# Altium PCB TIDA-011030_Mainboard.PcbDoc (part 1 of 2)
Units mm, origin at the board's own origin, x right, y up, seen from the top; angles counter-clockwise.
Board outline 65 x 19.54 mm, 4 copper layers (Top Layer, Inner Layer 1, Inner Layer 2, Bottom Layer), stack 1.586 mm thick; 113 components, 53 nets, 288 pads, 190 vias.
Unrouted connection lines stored in the file: 190.
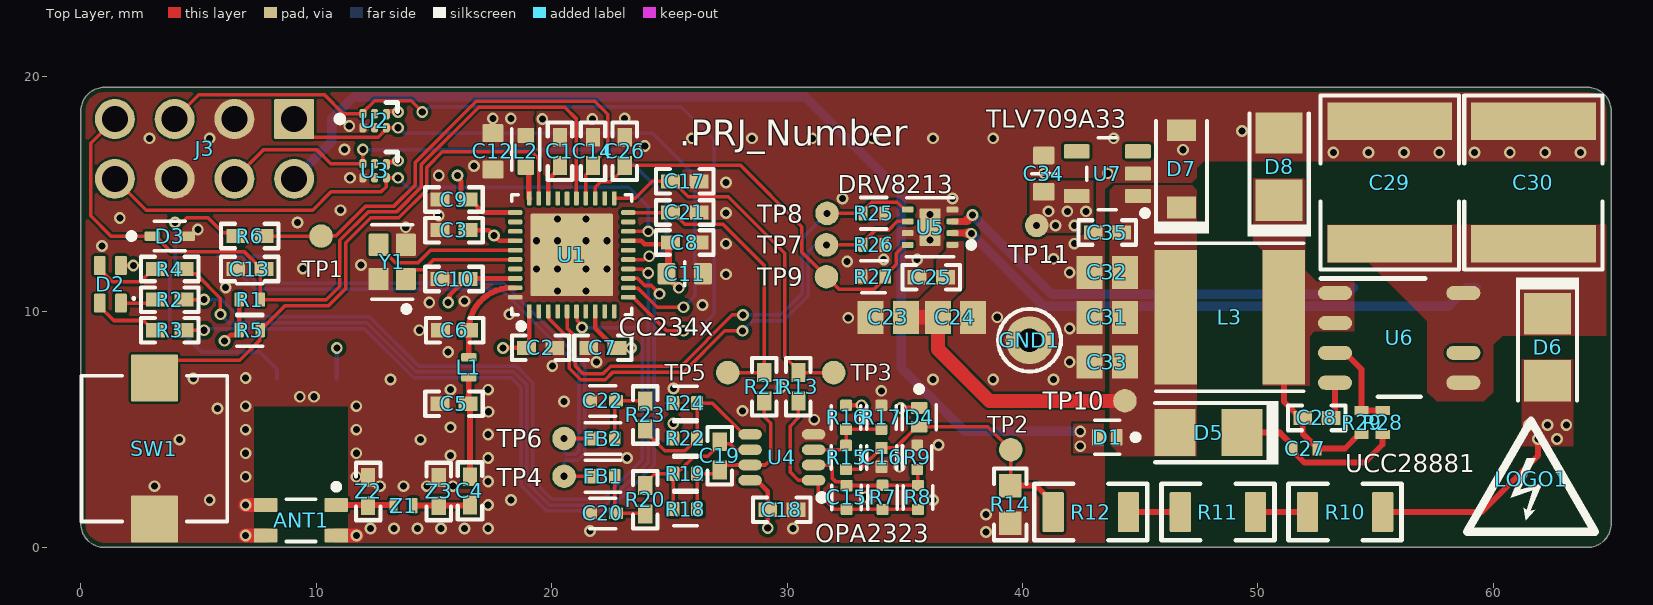
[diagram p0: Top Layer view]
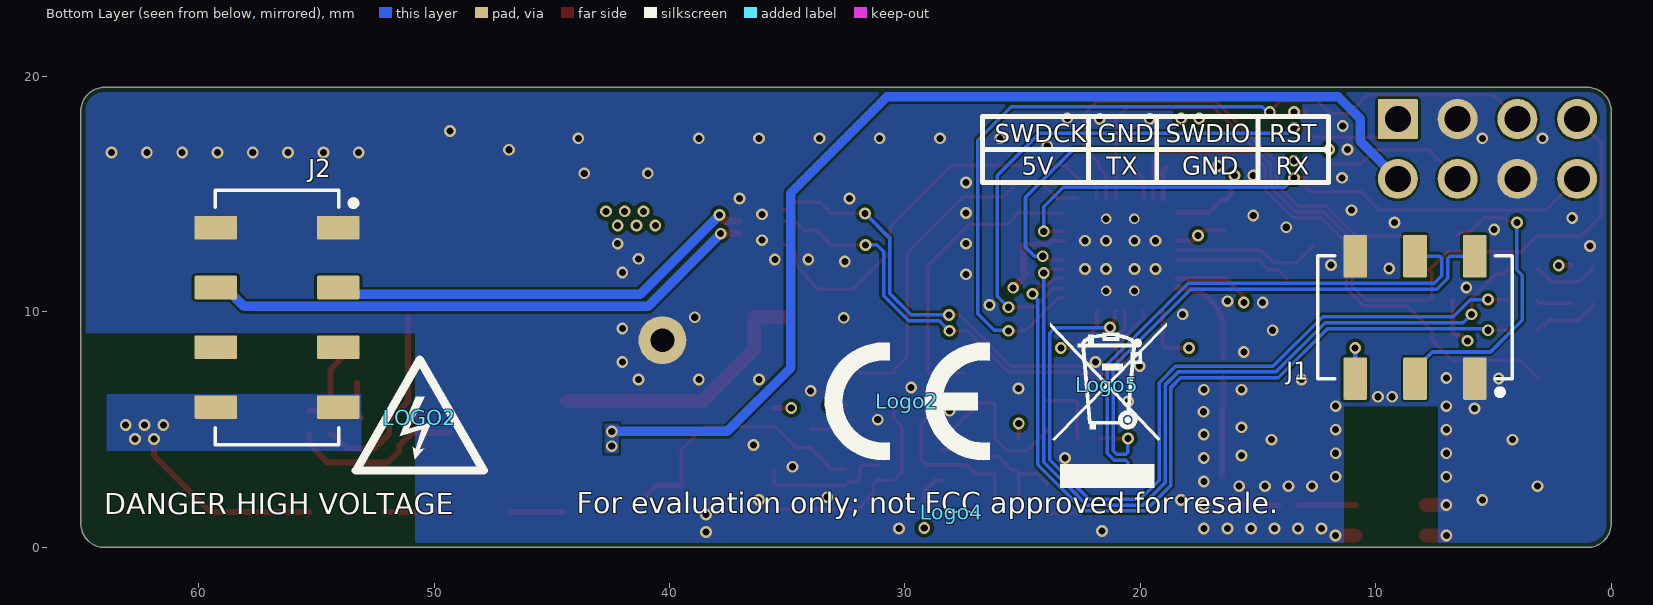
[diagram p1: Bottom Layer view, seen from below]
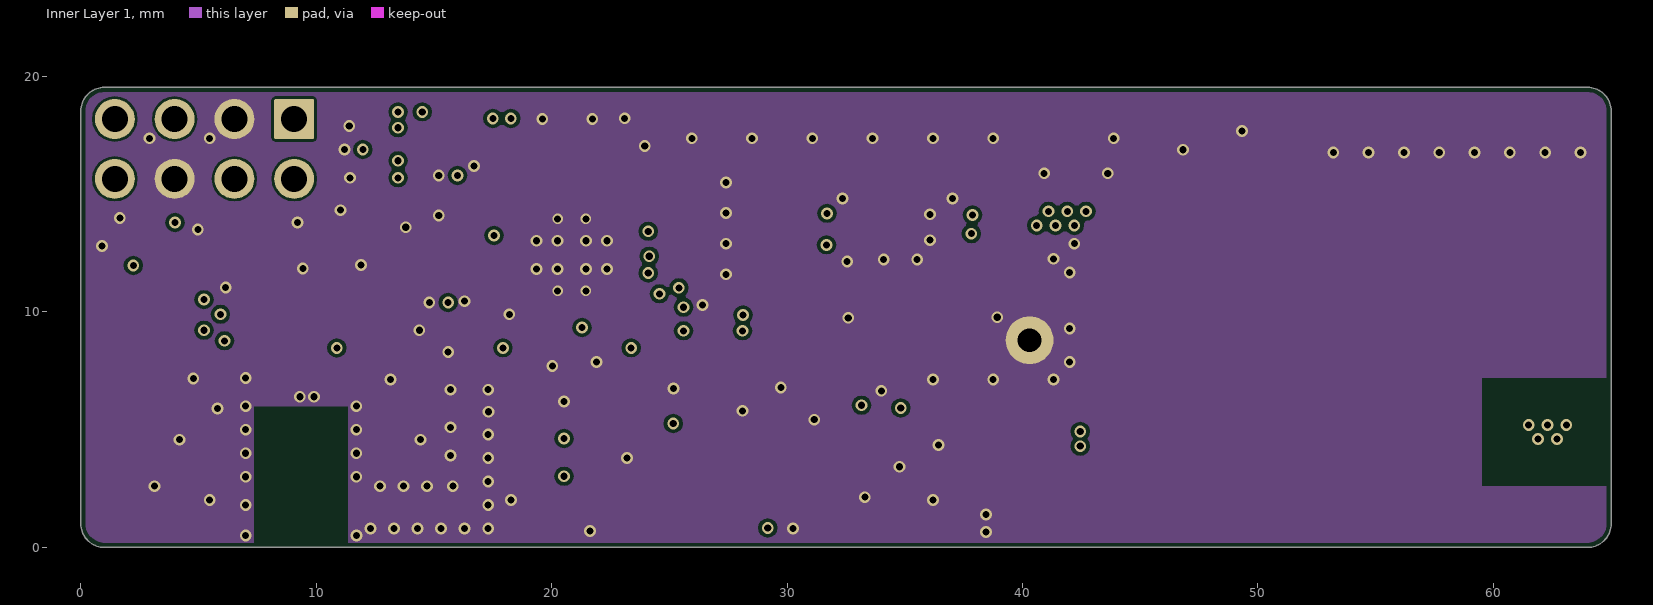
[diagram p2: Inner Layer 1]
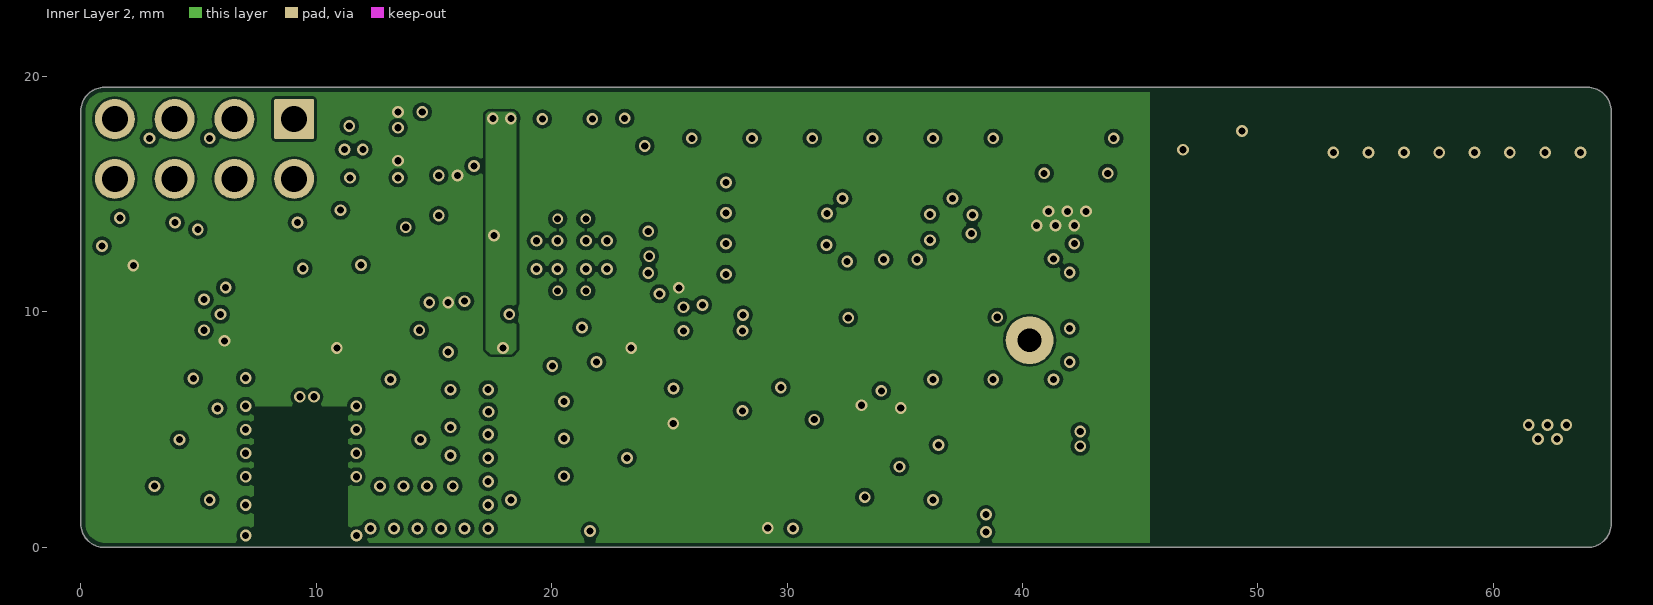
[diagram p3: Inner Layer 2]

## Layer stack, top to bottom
Top Solder: solder mask 0.0152, Solder Resist, Dk 3.8
Top Layer: signal copper 0.035
Dielectric 1: prepreg 0.2104, NP-155F, Dk 4.4
Inner Layer 1: signal copper 0.0152
Dielectric 2: core 1.065, NP-155F, Dk 4.43
Inner Layer 2: signal copper 0.0152
Dielectric 3: prepreg 0.2104, NP-155F, Dk 4.4
Bottom Layer: signal copper 0.035
Bottom Solder: solder mask 0.0152, Solder Resist, Dk 3.8

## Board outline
0,1 0,18.54 cw(c1,18.54) 1,19.54 64,19.54 cw(c64,18.54) 65,18.54 65,1 cw(c64,1) 64,0 1,0 cw(c1,1)

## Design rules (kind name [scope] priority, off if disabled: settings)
BoardOutlineClearance [All] p1: gap=0.2 ignorepadtopadclearanceinfootprint=FALSE
Clearance [All] p1: gap=0.102 ignorepadtopadclearanceinfootprint=FALSE except(0.127: Arc-Via Track-Via SMDPad-Via THPad-Via Via-Via Via-Fill Via-Poly Via-Region Via-Text; 0.25: Arc-Hole Track-Hole SMDPad-Hole THPad-Hole Via-Hole Fill-Hole Poly-Hole Region-Hole Text-Hole)
ComponentClearance [All] p1: gap=0.102 collisioncheckmode=3 verticalgap=0.102 showdistances=TRUE
DiffPairsRouting [All] p1: maxlimit=0.102 minlimit=0.102 mostfreqgap=0.102 toplayer_minwidth=0.102 toplayer_maxwidth=1816.048 toplayer_prefwidth=0.102 midlayer1_minwidth=0.102 midlayer1_maxwidth=1816.048 midlayer1_prefwidth=0.102 midlayer2_minwidth=0.102 midlayer2_maxwidth=1816.048 midlayer2_prefwidth=0.102 bottomlayer_minwidth=0.102 bottomlayer_maxwidth=1816.048 bottomlayer_prefwidth=0.102 maxuncoupledlength=12.7
Height [All] p1: minheight=0 maxheight=1816.048 prefheight=12.7
HoleSize [All] p1: absolutevalues=TRUE maxlimit=6.3 minlimit=0.2 maxpercent=80.000 minpercent=20.000
HoleToHoleClearance [All] p1: gap=0.25 allowstackedmicrovias=FALSE
MaxMinImpedance 50OHM [All] p1: minimum=48.00 maximum=52.00
MinimumAnnularRing [All] p1: minimumring=0.076
MinimumSolderMaskSliver [All] p1: minsoldermaskwidth=0
PlaneClearance [All] p1: clearance=0.102
PlaneConnect PlaneConnectPowerPads [InPadClass('PowerPads')] p1: planeconnectstyle=Direct reliefexpansion=0.508 reliefentries=4 reliefconductorwidth=0.254 reliefairgap=0.254
PlaneConnect [All] p2: pad.planeconnectstyle=Relief pad.reliefexpansion=0.3 pad.reliefentries=4 pad.reliefconductorwidth=0.102 pad.reliefairgap=0.102 via.planeconnectstyle=Direct via.reliefexpansion=0.3 via.reliefentries=4 via.reliefconductorwidth=0.127 via.reliefairgap=0.127
PolygonConnect PolygonConnectPowerPads [All vs (InPadClass('PowerPads'))] p1: connectstyle=Direct reliefconductorwidth=0.254 reliefentries=4 polygonreliefangle="90 Angle" airgapwidth=0.254
PolygonConnect [All] p2: thpad.connectstyle=Relief thpad.reliefconductorwidth=0.102 thpad.reliefentries=4 thpad.polygonreliefangle="90 Angle" thpad.airgapwidth=0.102 smdpad.connectstyle=Relief smdpad.reliefconductorwidth=0.102 smdpad.reliefentries=4 smdpad.polygonreliefangle="90 Angle" smdpad.airgapwidth=0.102 via.connectstyle=Direct via.reliefconductorwidth=0.127 via.reliefentries=4 via.polygonreliefangle="90 Angle" via.airgapwidth=0.127
RoutingVias [All] p1: holewidth=0.3 width=0.5 viastyle="Through Hole" minholewidth=0.2 minwidth=0.45 maxholewidth=6.3 maxwidth=6.55
SilkToBoardRegionClearance [Not ((IsComment or IsDesignator) And (Hide <> 'False')) and not InRegion(1000,500,4000,800)] p1:
SilkToSilkClearance [All] p1: silktosilkclearance=0
SilkToSolderMaskClearance [IsPad] p1: minsilkscreentomaskgap=0.102 clearancetoexposedcopper=TRUE
SolderMaskExpansion [All] p1: expansion=0.075 istentingtop=FALSE
SupplyNets "Schematic Supply Nets_4" [InNet('GND')] p1: voltage=0.000
SupplyNets "Schematic Supply Nets_3" [InNet('3.3V')] p2: voltage=0.000
SupplyNets "Schematic Supply Nets_1" [InNet('VDDR')] p3: voltage=0.000
SupplyNets "Schematic Supply Nets" [InNet('5V')] p4: voltage=0.000
Width "50 OHM" [InNetClass('50OHM')] p1: maxlimit=0.358 minlimit=0.1 preferedwidth=0.248 midlayer1_maxwidth=0.274 midlayer1_prefwidth=0.186 midlayer2_maxwidth=0.274 midlayer2_prefwidth=0.186 bottomlayer_maxwidth=0.357 impedanceprofiledriven=TRUE impedanceprofileid={30C50C51-8CC3-4552-90F9-A8ABCBFF07AD} impedanceprofilevalue=50.000000 minimp=50.000000 maximp=50.000000 favimp=50.000000
Width [All] p2: maxlimit=1816.048 minlimit=0.102 preferedwidth=0.102
19 further rules are at their usual default settings.

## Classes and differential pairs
net class HV: Line NetC27_2 NetC29_1
component class TIDA-011030_Mainboard_RelayDRV: C23 C24 C25 C26 R25 R26 R27 TP7 TP8 TP9 U5
component class TIDA-011030_Mainboard_Metering: C15 C16 C17 C18 C19 C20 C21 C22 D4 FB1 FB2 R7 R8 R9 R10 R11 R12 R13 R14 R15 R16 R17 R18 R19 R20 R21 R22 R23 R24 TP2 TP3 TP4 TP5 TP6 U4
component class TIDA-011030_Mainboard_Power: C27 C28 C29 C30 C31 C32 C33 C34 C35 D5 D6 D7 D8 L3 R28 R29 TP10 TP11 U6 U7
component class TIDA-011030_Mainboard_MCU: ANT1 C1 C2 C3 C4 C5 C6 C7 C8 C9 C10 C11 C12 C13 C14 D1 D2 D3 J1 J2 J3 L1 L2 R1 R2 R3 R4 R5 R6 SW1 TP1 U1 U2 U3 Y1 Z1 Z2 Z3
component class TIDA-011030_Mainboard_Hardware: GND1 LOGO1 Logo2 LOGO2 Logo4 Logo5 ZZ1 ZZ2 ZZ3
component class AssemblyNote: ZZ1 ZZ2 ZZ3
differential pair I: +I_P -I_N

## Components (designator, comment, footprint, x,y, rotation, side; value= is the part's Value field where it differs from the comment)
ANT1 "2450AT18D0100001E" FP-2450AT18D0100001E_1206-MFG 9.35,1.15 r180 top
C1 "GCM155R71C104KA55D" 0402 20.35,16.825 r270 top value=0.1uF
C2 "GCM155R71C104KA55D" 0402 19.525,8.475 r0 top value=0.1uF
C3 "GCM155R71C104KA55D" 0402 15.85,13.475 r180 top value=0.1uF
C4 "04025A150FAT2A" 0402 16.525,2.4 r270 top value=15pF
C5 "GRM1555C1H1R5CA01D" 0402 15.85,6.1 r180 top value=1.5pF
C6 "GRM1555C1H1R5CA01D" 0402 15.875,9.225 r180 top value=1.5pF
C7 "GCM155R71C104KA55D" 0402 22.175,8.475 r180 top value=0.1uF
C8 "GCM155R71C104KA55D" 0402 25.65,12.95 r0 top value=0.1uF
C9 "GCM155R71C104KA55D" 0402 15.85,14.775 r180 top value=0.1uF
C10 "GCM155R71C104KA55D" 0402 15.85,11.4 r180 top value=0.1uF
C11 "GRT188D71A106ME13D" FP-GRT188D71A106ME13D_0603-MFG 25.65,11.625 r0 top value=10µF
C12 "GRT188D71A106ME13D" FP-GRT188D71A106ME13D_0603-MFG 17.5,16.825 r270 top value=10µF
C13 "GCM155R71C104KA55D" 0402 7.175,11.825 r180 top value=0.1uF
C14 "GRM155R71H681KA01D" 0402 21.75,16.825 r90 top value=680pF
C15 "885012005058" FP-885012005058_0402-MFG 32.527,2.121 r270 top value=33pF
C16 "C0402C222F3GAC7867" FP-C0402C222F3GAC7867_0402-MFG 34.013,3.825 r90 top value=2.2nF
C17 "GRM155R71H681KA01D" 0402 25.65,15.55 r0 top value=680pF
C18 "GCM155R71C104KA55D" 0402 29.775,1.6 r0 top value=0.1uF
C19 "GRM1555C1H471JA01D" 0402 27.138,3.89 r90 top value=470pF
C20 "04025A101JAT2A" FP-04025A101JAT2A_0402-MFG 22.175,1.446 r0 top value=100pF
C21 "GRM155R71H681KA01D" 0402 25.65,14.229 r0 top value=680pF
C22 "04025A101JAT2A" FP-04025A101JAT2A_0402-MFG 22.175,6.225 r180 top value=100pF
C23 "GRM21BR61A476ME15L" 0805L 34.298,9.775 r180 top value=47uF
C24 "GRM21BR61A476ME15L" 0805L 37.15,9.775 r0 top value=47uF
C25 "GCM155R71C104KA55D" 0402 36.12,11.475 r180 top value=0.1uF
C26 "GRM155R71H681KA01D" 0402 23.1,16.825 r90 top value=680pF
C27 "GRM155R71H153KA12D" 0402S 52,4.2 r0 top value=0.015uF
C28 "GRM155R61C105MA12D" 0402 52.5,5.5 r180 top value=1uF
C29 "C5750X6S2W225K250KA" 2220_280 55.6,15.5 r90 top value=2.2uF
C30 "C5750X6S2W225K250KA" 2220_280 61.7,15.5 r90 top value=2.2uF
C31 "GRM21BR61A476ME15L" 0805L 43.6,9.775 r180 top value=47uF
C32 "GRM21BR61A476ME15L" 0805L 43.6,11.677 r180 top value=47uF
C33 "GRM21BR61A476ME15L" 0805L 43.6,7.875 r180 top value=47uF
C34 "GRT188D71A106ME13D" FP-GRT188D71A106ME13D_0603-MFG 40.9,15.875 r90 top value=10µF
C35 "GCM155R71C104KA55D" 0402 43.6,13.375 r180 top value=0.1uF
D1 "PMEG3005ELS-QYL" FP-PMEG3005ELS-QYL_DFN1006BD-2-0 43.6,4.677 r180 top
D2 "150066M153000" WL-SFCD0606_RGB 1.25,11.175 r180 top value=RGB
D3 "ESD321DYAR" DYA0002A-MFG 3.775,13.225 r0 top
D4 "PMEG3005ELS-QYL" FP-PMEG3005ELS-QYL_DFN1006BD-2-0 35.605,5.525 r270 top
D5 "CD1408-FU1600" Diode_1408 47.9,4.875 r180 top value=600V
D6 "CD1408-FU1600" Diode_1408 62.3,8.5 r270 top value=600V
D7 "DDZ8V2C-7" SOD-123 46.75,16.075 r90 top value=8.2V
D8 "CD1408-FU1600" Diode_1408 50.9,16.175 r90 top value=600V
FB1 "74269244182" FP-74269244182_0402-MFG 22.175,3.023 r180 top
FB2 "74269244182" FP-74269244182_0402-MFG 22.175,4.625 r180 top
GND1 "5001" Keystone5001 40.3,8.8 r0 top
J1 "61000621821" FP-61000621821_HDR6-MFG 8.33,9.77 r0 bottom locked
J2 "61000821821" FP-61000821821_CONN_RCPT_8-MFG 56.67,9.77 r270 bottom locked
J3 "61300821121" FP-61300821121_HDR8-MFG 5.25,16.925 r180 top
L1 "LQG15WZ2N8B02D" LQG15WZ_02 16.475,7.65 r90 top value=2.8nH
L2 "LQM18DH100M70L" FP-LQM18DH100M70L_0603-MFG 18.9,16.825 r90 top value=10uH
L3 "74404064102" WE-LQS_6045 48.8,9.775 r0 top
LOGO1 "DANGER HIGH VOLTAGE" IEC_HighVoltage_Small 61.6,2.9 r0 top
LOGO2 "DANGER HIGH VOLTAGE" IEC_HighVoltage_Small 50.6,5.5 r180 bottom
Logo2 "CE Mark" CE_Mark_5mm 29.9,6.2 r180 bottom
Logo4 "FCC disclaimer" FCC_disclaimer 28,1.5 r180 bottom
Logo5 "WEEE logo" WEEE_Minimum 21.4,6.9 r180 bottom
R1 "CRCW0402100KFKEDC" FP-CRCW0402100KFKEDC_0402-MFG 7.175,10.525 r180 top value=100k
R2 "ERJ-2RKF3300X" 0402 3.775,10.525 r0 top value=330
R3 "ERJ-2RKF3300X" 0402 3.775,9.225 r0 top value=330
R4 "ERJ-2RKF3300X" 0402 3.775,11.825 r0 top value=330
R5 "CRCW0402100KFKEDC" FP-CRCW0402100KFKEDC_0402-MFG 7.175,9.225 r180 top value=100k
R6 "RC0402FR-0733RL" 0402 7.175,13.225 r0 top value=33.0
R7 "ERA-2AEB913X" FP-ERA-2AEB913X_0402-MFG 34.053,2.125 r270 top value=91k
R8 "ERA-2AEB913X" FP-ERA-2AEB913X_0402-MFG 35.555,2.121 r270 top value=91k
R9 "ERA2AEB223X" FP-ERA2AEB223X_0402-MFG 35.525,3.823 r270 top value=22k
R10 "TNPV1206330KBEEN" TNPV1206 53.7,1.5 r0 top value=330k
R11 "TNPV1206330KBEEN" TNPV1206 48.3,1.5 r0 top value=330k
R12 "TNPV1206330KBEEN" TNPV1206 42.9,1.5 r0 top value=330k
R13 "RC0402FR-0733RL" 0402 30.475,6.825 r90 top value=33.0
R14 "RT0603BRD072KL" 0603 39.475,1.825 r90 top value=2.00k
R15 "ERA2AEB223X" FP-ERA2AEB223X_0402-MFG 32.502,3.823 r90 top value=22k
R16 "ERA-2AEB913X" FP-ERA-2AEB913X_0402-MFG 32.502,5.525 r90 top value=91k
R17 "ERA-2AEB913X" FP-ERA-2AEB913X_0402-MFG 34.003,5.525 r270 top value=91k
R18 "RT0402BRD0741K2L" FP-RT0402BRD0741K2L_0402-MFG 25.675,1.625 r180 top value=41.2k
R19 "RT0402BRD0741K2L" FP-RT0402BRD0741K2L_0402-MFG 25.675,3.127 r180 top value=41.2k
R20 "ERA-2AEB102X" 0402 23.975,2.025 r90 top value=1.00k
R21 "RC0402FR-0733RL" 0402 29.025,6.825 r90 top value=33.0
R22 "RT0402BRD0741K2L" FP-RT0402BRD0741K2L_0402-MFG 25.675,4.629 r0 top value=41.2k
R23 "ERA-2AEB102X" 0402 23.975,5.625 r270 top value=1.00k
R24 "RT0402BRD0741K2L" FP-RT0402BRD0741K2L_0402-MFG 25.675,6.131 r180 top value=41.2k
R25 "CRCW0402100KFKEDC" FP-CRCW0402100KFKEDC_0402-MFG 33.673,14.188 r180 top value=100k
R26 "CRCW0402100KFKEDC" FP-CRCW0402100KFKEDC_0402-MFG 33.67,12.85 r180 top value=100k
R27 "RC0402FR-078K2L" FP-RC0402FR-078K2L_0402-MFG 33.67,11.5 r0 top value=8.2k
R28 "CRCW040238K3FKED" 0402S 55.3,5.3 r270 top value=38.3k
R29 "ERJ-2RKF1002X" 0402S 54.4,5.3 r90 top value=10.0k
SW1 "430133050816" FP-430133050816_SMD2-MFG 3.125,4.2 r90 top
TP1 "TP_SM_1MM" TP_SM_1MM 10.2,13.225 r0 top
TP2 "TP_SM_1MM" TP_SM_1MM 39.5,4.15 r0 top
TP3 "TP_SM_1MM" TP_SM_1MM 31.975,7.425 r0 top
TP4 "TP_SM_1MM" TP_SM_1MM 20.525,3.023 r0 top
TP5 "TP_SM_1MM" TP_SM_1MM 27.475,7.425 r0 top
TP6 "TP_SM_1MM" TP_SM_1MM 20.525,4.625 r0 top
TP7 "TP_SM_1MM" TP_SM_1MM 31.67,12.85 r0 top
TP8 "TP_SM_1MM" TP_SM_1MM 31.695,14.188 r0 top
TP9 "TP_SM_1MM" TP_SM_1MM 31.67,11.5 r0 top
TP10 "TP_SM_1MM" TP_SM_1MM 44.35,6.225 r0 top
TP11 "TP_SM_1MM" TP_SM_1MM 40.6,13.675 r0 top
U1 "CC2340R53E0RKPR" RKP0040B-MFG 20.85,12.425 r90 top
U2 "TPD2E001DRYR" DRY0006A 12.475,18.125 r270 top
U3 "TPD2E001DRYR" DRY0006A 12.475,16 r270 top
U4 "TLV9002IDDFR" DDF0008A_N 29.775,3.825 r180 top
U5 "DRV8213DSG" DSG0008A-MFG 36.07,13.6 r180 top
U6 "UCC28881DR" D0007A_N 56,8.9 r0 top
U7 "TLV709A33DBVR" DBV0005A-MFG 43.6,15.875 r180 top
Y1 "TZ3908AAAO43" FP-TZ3908AAAO43_SMT4_2MM05_1MM65-MFG 13.225,12.125 r90 top
Z1 "LQG15WZ1N9S02D" LQG15WZ_02 13.7,1.775 r0 top value=1.9nH
Z2 "GRM1555C1H1R5CA01D" 0402 12.2,2.375 r90 top value=1.5pF
Z3 "GRM1555C1H1R5CA01D" 0402 15.2,2.375 r90 top value=1.5pF
ZZ1 "These assemblies are ESD sensitive, ESD precautions shall be observed." AssemblyNote 5.099,28.059 r0 top
ZZ2 "These assemblies must be clean and free from flux and all contaminants. Use of no clean flux is not acceptable." AssemblyNote 5.099,25.81 r0 top
ZZ3 "These assemblies must comply with workmanship standards IPC-A-610 Class 2, unless otherwise specified." AssemblyNote 5.099,23.561 r0 top

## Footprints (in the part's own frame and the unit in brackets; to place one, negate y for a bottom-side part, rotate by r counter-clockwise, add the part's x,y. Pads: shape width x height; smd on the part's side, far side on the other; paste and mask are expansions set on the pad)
0402 [mm] "0402 from SM-752 data"
  rect 0.8x0.6 smd: 1(-0.6,0) 2(0.6,0)
  silkscreen extent -1.22,-0.52 1.22,0.52, body extent -0.55,-0.3 0.55,0.3, height 0.6
0402S [mil] "Based on C0402S footprint from PADS legacy"
  rect 15x24 smd: 1(-20,0) 2(20,0)
  body extent -22,-12 22,12, height 24
0603 [mm] "0603 from SM-752 data"
  rect 1x0.95 smd: 1(-0.8,0) 2(0.8,0)
  silkscreen extent -1.52,-0.69 1.52,0.69, body extent -0.87,-0.47 0.87,0.47, height 1
0805L [mm] "0805 from SM-752 data"
  rect 1.1x1.4 smd: 1(-0.75,0) 2(0.75,0)
  body extent -1.1,-0.72 1.1,0.72, height 1.45
2220_280 [mm] "Chip Capacitor, Body 5.7x5.0mm, IPC Medium Density"
  rect 1.6x5.3 smd: 1(-2.6,0) 2(2.6,0)
  silkscreen extent -3.69,-2.94 3.69,2.94, body extent -2.95,-2.62 2.95,2.62, height 2.8
AssemblyNote [mm] "Assembly Note"
CE_Mark_5mm [mm] "Minimum text height for CE Mark"
  silkscreen extent -3.5,-2.5 3.5,2.5
D0007A_N [mm] "SOIC, 7-Leads, Body 4.9x3.9mm, Pitch 1.27mm, IPC Medium Density"
  oval 1.45x0.6 smd: 1(-2.725,1.905) 2(-2.725,0.635) 3(-2.725,-0.635) 4(-2.725,-1.905) 5(2.725,-1.905) 6(2.725,-0.635) 8(2.725,1.905)
  silkscreen extent -3.32,-2.5 1.1,2.52, body extent -3.01,-2.45 3.01,2.45, height 1.75
DBV0005A-MFG [mm]
  rrect17% 1.1x0.6 smd paste+0 mask+0: 1(-1.3,0.95) 2(-1.3,0) 3(-1.3,-0.95) 4(1.3,-0.95) 5(1.3,0.95)
  silkscreen extent -1.73,-1.53 0.87,1.8, body extent -1.95,-1.78 1.95,1.78, height 0.25
DDF0008A_N [mm] "SOT-23-THN-8, IPC Medium Density"
  oval 1x0.45 smd: 1(-1.35,0.975) 2(-1.35,0.325) 3(-1.35,-0.325) 4(-1.35,-0.975) 5(1.35,-0.975) 6(1.35,-0.325) 7(1.35,0.325) 8(1.35,0.975)
  body extent -1.41,-1.45 1.41,1.45, height 0.9
Diode_1408 [mm] "On Semi recommended land pattern for SOD-123"
  rect 1.75x2 smd: 1(-1.425,0) 2(1.425,0)
  silkscreen extent -2.97,-1.35 2.26,1.35, body extent -1.8,-1.05 1.8,1.05, height 1.35
DRY0006A [mm] "USON-6"
  rrect67% 0.45x0.3 smd paste-0.05 mask-0.05: 1(-0.275,0.5)
  rrect67% 0.4x0.3 smd paste-0.05 mask-0.05: 2(-0.3,0) 3(-0.3,-0.5) 4(0.3,-0.5) 5(0.3,0) 6(0.3,0.5)
  body extent -0.5,-0.72 0.5,0.73, height 0.58
DSG0008A-MFG [mm]
  rrect40% 0.5x0.25 smd paste+0 mask+0: 1(-0.95,0.75) 2(-0.95,0.25) 3(-0.95,-0.25) 4(-0.95,-0.75) 5(0.95,-0.75) 6(0.95,-0.25) 7(0.95,0.25) 8(0.95,0.75)
  rrect11% 0.9x1.6 smd paste-1000 mask+0: 9(0,0)
  silkscreen extent -1.88,-1.25 1,1.25, body extent -1.3,-1.15 1.3,1.15, height 0.25
DYA0002A-MFG [mm] "Recommended Land Pattern"
  rrect25% 0.67x0.4 smd paste+0 mask+0: 1(-0.74,0) 2(0.74,0)
  silkscreen extent -1.75,-0.63 0.65,0.63, body extent -0.8,-0.39 0.8,0.39, height 0.77
FCC_disclaimer [mm]
FP-2450AT18D0100001E_1206-MFG [mm]
  rrect17% 1x0.6 smd paste+0 mask+0: 1(-1.5,-0.65) 2(1.5,-0.65) 3(1.5,0.65) 4(-1.5,0.65)
  silkscreen extent -1.63,-1.55 0.63,0.9, body extent -2.1,-1.05 2.1,1.05, height 0.25
FP-04025A101JAT2A_0402-MFG [mm]
  rrect20% 0.6x0.5 smd paste+0 mask+0: 1(-0.55,0) 2(0.55,0)
  silkscreen extent -0.55,-0.65 0.55,0.65, body extent -0.95,-0.4 0.95,0.4, height 0.25
FP-61000621821_HDR6-MFG [mm] "Recommended Land Pattern"
  rrect10% 1x1.8 smd paste+0 mask+0: 1(-2.54,2.6) 2(-2.54,-2.6) 3(0,2.6) 4(0,-2.6) 5(2.54,2.6) 6(2.54,-2.6)
  silkscreen extent -4.14,-2.62 4.14,3.3, body extent -4.06,-3.35 4.06,3.35, height 7.6
FP-61000821821_CONN_RCPT_8-MFG [mm] "Recommended Land Pattern"
  rrect10% 1x1.8 smd paste+0 mask+0: 1(-3.81,2.6) 2(-3.81,-2.6) 3(-1.27,2.6) 4(-1.27,-2.6) 5(1.27,2.6) 6(1.27,-2.6) 7(3.81,2.6) 8(3.81,-2.6)
  silkscreen extent -5.41,-2.62 5.41,3.37, body extent -5.33,-3.35 5.33,3.35, height 7.6
FP-61300821121_HDR8-MFG [mm]
  rrect6% 1.7x1.7 hole 1.1 paste-2539.97 mask+0: 1(-3.81,-1.27)
  round 1.7 hole 1.1 paste-2539.97 mask+0: 2(-3.81,1.27) 3(-1.27,-1.27) 4(-1.27,1.27) 5(1.27,-1.27) 6(1.27,1.27) 7(3.81,-1.27) 8(3.81,1.27)
  body extent -5.33,-2.72 5.33,2.72, height 0.25
FP-74269244182_0402-MFG [mm]
  rrect20% 0.5x0.6 smd paste+0 mask+0: 1(-0.5,0) 2(0.5,0)
  silkscreen extent -0.75,-0.67 0.75,0.67, body extent -0.85,-0.4 0.85,0.4, height 0.25
FP-430133050816_SMD2-MFG [mm] "Recommended Land Pattern"
  rrect5% 2x2 smd paste+0 mask+0: 1(-3,0) 2(3,0)
  silkscreen extent -3.1,-3.1 3.1,3.1, body extent -3.35,-3 3.35,3, height 5.2
FP-885012005058_0402-MFG [mm]
  rrect20% 0.5x0.5 smd paste+0 mask+0: 1(-0.5,0) 2(0.5,0)
  silkscreen extent -0.53,-0.63 0.53,0.63, body extent -0.85,-0.38 0.85,0.38, height 0.25
FP-C0402C222F3GAC7867_0402-MFG [mm]
  rrect19% 0.52x0.52 smd paste+0 mask+0: 1(-0.4,0) 2(0.4,0)
  silkscreen extent -0.5,-0.64 0.5,0.64, body extent -0.8,-0.4 0.8,0.4, height 0.25
FP-CRCW0402100KFKEDC_0402-MFG [mm]
  rrect25% 0.4x0.6 smd paste+0 mask+0: 1(-0.45,0) 2(0.45,0)
  silkscreen extent -0.55,-0.67 0.55,0.67, body extent -0.75,-0.4 0.75,0.4, height 0.25
FP-ERA2AEB223X_0402-MFG [mm]
  rrect21% 0.475x0.5 smd paste+0 mask+0: 1(-0.512,0) 2(0.512,0)
  silkscreen extent -0.5,-0.63 0.5,0.63, body extent -0.85,-0.4 0.85,0.4, height 0.25
FP-ERA-2AEB913X_0402-MFG [mm] "Recommended Land Pattern"
  rrect21% 0.475x0.5 smd paste+0 mask+0: 1(-0.512,0) 2(0.512,0)
  silkscreen extent -0.5,-0.63 0.5,0.63, body extent -0.5,-0.25 0.5,0.25, height 0.4
FP-GRT188D71A106ME13D_0603-MFG [mm] "Recommended Land Pattern"
  rrect13% 0.75x0.9 smd paste+0 mask+0: 1(-0.775,0) 2(0.775,0)
  silkscreen extent 0,-0.5 0,0.5, body extent -1.25,-0.6 1.25,0.6, height 0.25
FP-LQM18DH100M70L_0603-MFG [mm]
  rrect15% 0.65x0.7 smd paste+0 mask+0: 1(-0.675,0) 2(0.675,0)
  silkscreen extent -0.8,-0.6 0.95,0.6, body extent -1.1,-0.58 1.1,0.58, height 0.25
FP-PMEG3005ELS-QYL_DFN1006BD-2-0 [mm]
  rrect20% 0.5x0.7 smd paste-1000 mask+0: 1(-0.4,0) 2(0.4,0)
  silkscreen extent -1.33,-0.72 0.53,0.72, body extent -0.75,-0.45 0.75,0.45, height 0.25
FP-RC0402FR-078K2L_0402-MFG [mm]
  rrect20% 0.5x0.6 smd paste+0 mask+0: 1(-0.5,0) 2(0.5,0)
  silkscreen extent -0.5,-0.67 0.5,0.67, body extent -0.85,-0.4 0.85,0.4, height 0.25
FP-RT0402BRD0741K2L_0402-MFG [mm]
  rrect20% 0.5x0.6 smd paste+0 mask+0: 1(-0.5,0) 2(0.5,0)
  silkscreen extent -0.5,-0.71 0.5,0.7, body extent -0.85,-0.4 0.85,0.4, height 0.25
FP-TZ3908AAAO43_SMT4_2MM05_1MM65-MFG [mm]
  rrect12% 0.95x0.85 smd paste+0 mask+0: 1(-0.725,-0.575) 2(0.725,-0.575) 3(0.725,0.575) 4(-0.725,0.575)
  silkscreen extent -2.12,-0.87 1.58,0.87, body extent -1.3,-1.1 1.3,1.1, height 0.25
IEC_HighVoltage_Small [mm]
  silkscreen extent -2.72,-2.24 2.72,2.47
Keystone5001 [mil] "For Keystone 500x miniature loop terminals"
  round 80 hole 40: 1(0,0)
  silkscreen extent -52,-52 52,52, body extent -49,-49 49,49, height 182
LQG15WZ_02 [mm] "MuRata recommended land pattern"
  rrect29% 0.35x0.65 smd: 1(-0.425,0) 2(0.425,0)
  body extent -0.52,-0.32 0.52,0.32, height 0.6
RKP0040B-MFG [mm]
  rrect50% 0.6x0.2 smd paste+0 mask+0: 1(-2.4,1.8) 2(-2.4,1.4) 3(-2.4,1) 4(-2.4,0.6) 5(-2.4,0.2) 6(-2.4,-0.2) 7(-2.4,-0.6) 8(-2.4,-1) 9(-2.4,-1.4) 10(-2.4,-1.8) 21(2.4,-1.8) 22(2.4,-1.4) 23(2.4,-1) 24(2.4,-0.6) 25(2.4,-0.2) 26(2.4,0.2) 27(2.4,0.6) 28(2.4,1) 29(2.4,1.4) 30(2.4,1.8)
  rrect50% 0.2x0.6 smd paste+0 mask+0: 11(-1.8,-2.4) 12(-1.4,-2.4) 13(-1,-2.4) 14(-0.6,-2.4) 15(-0.2,-2.4) 16(0.2,-2.4) 17(0.6,-2.4) 18(1,-2.4) 19(1.4,-2.4) 20(1.8,-2.4) 31(1.8,2.4) 32(1.4,2.4) 33(1,2.4) 34(0.6,2.4) 35(0.2,2.4) 36(-0.2,2.4) 37(-0.6,2.4) 38(-1,2.4) 39(-1.4,2.4) 40(-1.8,2.4)
  rrect3% 3.5x3.5 smd paste-1000 mask+0: 41(0,0)
  silkscreen extent -3.15,-2.55 2.55,2.55, body extent -2.8,-2.8 2.8,2.8, height 0.25
SOD-123 [mm] "On Semi recommended land pattern"
  rect 0.915x1.22 smd: 1(-1.637,0) 2(1.637,0)
  silkscreen extent -2.74,-1.17 2.03,1.17, body extent -1.93,-0.9 1.93,0.9, height 1.35
TNPV1206 [mm] "VISHAY"
  rrect11% 0.9x1.7 smd: 1(-1.6,0) 2(1.6,0)
  silkscreen extent -2.4,-1.2 2.4,1.2, body extent -1.67,-0.87 1.67,0.87, height 0.65
TP_SM_1MM [mm] "1mm Test Point, SMT"
  round 1 smd paste-0.5: 1(0,0)
WE-LQS_6045 [mm] "SMD Power Inductor, 2-Leads, body 6x6mm"
  rect 1.8x5.7 smd: 1(2.3,0) 2(-2.3,0)
  silkscreen extent -3.15,-3.15 3.15,3.15, body extent -3,-3 3,3, height 4.52
WEEE_Minimum [mm] "WEEElie bin"
  silkscreen extent -2.42,-4.38 2.52,2.65
WL-SFCD0606_RGB [mm] "SMD, 4-Leads, Body 1.6x1.6mm"
  rrect20% 0.5x0.8 smd: 1(-0.45,0.8) 2(0.45,0.8) 3(0.45,-0.8) 4(-0.45,-0.8)
  silkscreen extent -1.05,0.55 -0.95,0.65, body extent -0.8,-0.8 0.8,0.8, height 0.4

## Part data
ANT1: library part CMP-0121196-1, "2.4GHz Chip RF Antenna 2.4GHz ~ 2.5GHz 1.5dBi Solder Surface Mount", Digikey Part Number=712-2450AT18D0100001ECT-ND, Manufacturer=Johanson, Max Frequency=2.5GHz, Operating Temperature Range="-40°C to +125°C", Power_W=3W
C1 C2 C3 C7 C8 C9 C10 C13 C18 C25 C35: library part CMP-0006351-2, "CAP, CERM, 0.1 uF, 16 V, +/- 10%, X7R, 0402", Cap_Case=0402, Manufacturer=MuRata, Supplier Part Number 1=490-4759-2-ND, TempCo=X7R, Tolerance_%=10%, Value1=Unknown, Value2=16V, ValueDisplayed=0.1uF
C4: library part CMP-0078217-1, "CAP, CERM, 15 pF, 50 V,+/- 1%, C0G/NP0, 0402", Cap_Case=0402, Manufacturer=AVX, Supplier Part Number 1=478-5126-1-ND, TempCo=C0G/NP0, Tolerance_%=1%, Value2=50V, ValueDisplayed=15pF
C5 C6 Z2 Z3: library part CMP-0006433-2, "CAP, CERM, 1.5 pF, 50 V, +/- 5%, C0G/NP0, 0402", Cap_Case=0402, Manufacturer=MuRata, Supplier Part Number 1=14T3290, TempCo=C0G/NP0, Tolerance_%=5%, Value1=Unknown, Value2=50V, ValueDisplayed=1.5pF
C11 C12 C34: library part CMP-0124993-1, "Multi-Layer Ceramic Capacitor 10uF 10V X7T ±20% 0603 Paper T/R", Manufacturer=Murata, Operating Temperature Range="-55°C to +125°C", TempCo=+22/-33%, Temperature Characteristic=X7T, Tolerance_%=20%, ValueDisplayed=10uF
C14 C17 C21 C26: library part CMP-0006695-2, "CAP, CERM, 680 pF, 50 V, +/- 10%, X7R, 0402", Cap_Case=0402, Manufacturer=MuRata, Supplier Part Number 1=490-1302-1-ND, TempCo=X7R, Tolerance_%=10%, Value1=Unknown, Value2=50V, ValueDisplayed=680pF
C15: library part CMP-0097306-1, "33 pF ±5% 50V Ceramic Capacitor C0G, NP0 0402 (1005 Metric)", Digikey Part Number=732-7472-1-ND, Manufacturer="Wurth Electronics", Mouser Part Number=710-885012005058, Operating Temperature Range="-55°C to +125°C", TempCo=30ppm/°C, Temperature Characteristic=NP0, Tolerance_%=5%, ValueDisplayed=33pF
C16: library part CMP-0097646-1, "2200 pF ±1% 25V Ceramic Capacitor C0G, NP0 0402 (1005 Metric)", Digikey Part Number=399-C0402C222F3GAC7867CT-ND, Manufacturer=KEMET, Operating Temperature Range="-55°C to +125°C", TempCo=30ppm/°C, Temperature Characteristic=C0G, Tolerance_%=1%, ValueDisplayed=2200pF
C19: library part CMP-0006470-2, "CAP, CERM, 470 pF, 50 V, +/- 5%, C0G/NP0, 0402", Cap_Case=0402, Manufacturer=MuRata, Supplier Part Number 1=490-1297-1-ND, TempCo=C0G/NP0, Tolerance_%=5%, Value1=Unknown, Value2=50V, ValueDisplayed=470pF
C20 C22: library part CMP-0092080-1, "100pF ±5% 50V Ceramic Capacitor C0G, NP0 0402 (1005 Metric)", Digikey Part Number=478-1082-1-ND, Manufacturer=AVX, Mouser Part Number=581-04025A101J, Operating Temperature Range="-55°C to +125°C", TempCo=30ppm/°C, Temperature Characteristic=C0G, Tolerance_%=5%, ValueDisplayed=100pF
C23 C24 C31 C32 C33: library part CMP-0078699-1, "CAP, CERM, 47 µF, 10 V,+/- 20%, X5R, 0805", Cap_Case=0805, Manufacturer=MuRata, Supplier Part Number 1=490-9961-1-ND, TempCo=X5R, Tolerance_%=20%, Value2=10V, ValueDisplayed=47µF
C27: library part CMP-0006679-2, "CAP, CERM, 0.015 uF, 50 V, +/- 10%, X7R, 0402", Cap_Case=0402, Manufacturer=MuRata, Supplier Part Number 1=490-4517-1-ND, TempCo=X7R, Tolerance_%=10%, Value1=Unknown, Value2=50V, ValueDisplayed=0.015uF
C28: library part CMP-0084375-1, "CAP, CERM, 1 µF, 16 V,+/- 20%, X5R, 0402", Cap_Case=0402, Manufacturer=MuRata, TempCo=X5R, Tolerance_%=20%, Value2=16V, ValueDisplayed=1µF
C29 C30: library part CMP-0009372-2, "CAP, CERM, 2.2 uF, 450 V, +/- 10%, X6S, 2220", Cap_Case=2220, Manufacturer=TDK, Supplier Part Number 1=445-7781-1-ND, TempCo=X6S, Tolerance_%=10%, Value1=Unknown, Value2=450V, ValueDisplayed=2.2uF
D1 D4: library part CMP-0123792-2, "Diode 30 V 500mA Surface Mount DFN1006BD-2", Digikey Part Number=1727-PMEG3005ELS-QYLTR-ND, Forward Current=0.5A, Manufacturer=Nexperia, Max Surge Forward Current=3A, Mouser Part Number=771-PMEG3005ELS-QYL, Operating Temperature Range="to +150°C", Peak Reverse Current=70uA, ValueDisplayed=24pF
D2: library part CMP-0067667-2, "LED, RGB, SMD", Color=RGB, Manufacturer="Wurth Elektronik", Power_TotalModule=78mW, Value1=0.078W, Value2=3.3V
D3: library part CMP-0125991-1, "0.9pF 3.6V ±30kV ESD protection diode with 6.8V 16A TLP clamping for USB 2.0 2-SOT-5X3 -55 to 150", Breakdown Voltage=4.5V, Clamping Voltage=6.3V, Digikey Part Number=296-ESD321DYARCT-ND, Manufacturer="Texas Instruments", Mouser Part Number=595-ESD321DYAR, Operating Temperature Range="-55°C to +150°C", ValueDisplayed=0.9pF
D5 D6 D8: library part CMP-0029015-2, "Diode, Ultrafast, 600 V, 1 A, 1408 Diode", Manufacturer=Bourns, Value1=1A, Value2=1.25V
D7: library part CMP-0085110-1, "Diode, Zener, 8.2 V, 500 mW, SOD-123", Manufacturer="Diodes Inc.", Power_W=500mW, Value1=0.5W
FB1 FB2: library part CMP-0091663-1, "1.8 kOhms @ 100MHz 1 Power, Signal Line Ferrite Bead 0402 (1005 Metric) 210mA 2.1Ohm", Digikey Part Number=732-74269244182CT-ND, Impedance At Frequency="1800Ω @ 100MHz", Manufacturer="Wurth Electronics", Mouser Part Number=710-74269244182, Operating Temperature Range="-55°C to +125°C", Test Frequency=1GHz, Tolerance_%=25%
GND1: library part CMP-0055138-2, "Test Point, Miniature, Black, TH", Color=Black, Manufacturer="Keystone Electronics", Supplier Part Number 1=36-5001-ND
J1: library part CMP-0128753-1, "WR-PHD 2.54 mm Dual Row SMT Socket Header 6 pins", Current_A=3A, Manufacturer="Wurth Electronics", Operating Temperature Range="-40°C to +105°C", Voltage_V=250V
J2: library part CMP-0128754-1, "CONNECTOR, RCPT, 8POS, 2ROW, 2.54MM", Current_A=3A, Manufacturer="Wurth Electronics", Operating Temperature Range="-40°C to +105°C", Voltage_V=250V
J3: library part CMP-0087153-1, "CONN HEADER VERT 8POS 2.54MM", Current_A=3A, Manufacturer="Wurth Electronics", Voltage_V=250V
L1: library part CMP-0080227-3, "Inductor, Multilayer, Air Core, 2.8 nH, 0.9 A, 0.08 ohm, AEC-Q200 Grade 1, SMD", Manufacturer=MuRata, Value1="0.08 ohm", Value2=0.9A, ValueDisplayed=2.8nH
L2: library part CMP-0050143-1, "10 µH Shielded Multilayer Inductor 300 mA 1.37Ohm Max 0603 (1608 Metric)", Digikey Part Number=490-LQM18DH100M70LCT-ND, Manufacturer=Murata, Mouser Part Number=81-LQM18DH100M70L, Operating Temperature Range="-55°C to +150°C", Self Resonant Frequency=32MHz, Test Frequency=1MHz, Tolerance_%=20%
L3: library part CMP-03913-61645236-2, "POWER INDUCTOR General Purpose Inductor, 1000uH, 10%, 1 Element, SMD, 2424", Ambient Temperature Range High=85°C, Ambient Temperature Range Low=-40°C, Case/Package=Nonstandard, Current Rating=300mA, DC Resistance (DCR)=4.783Ω, Inductance=1mH, Inductance Tolerance=20%, Max Operating Temperature=125°C, Saturation Current=365mA, Self Resonant Frequency=1.86MHz, Test Frequency=100kHz
LOGO1 LOGO2: library part CMP-0074835-1, "IEC 61010-1 High Voltage Warning"
Logo2: library part CMP-0074844-2, Manufacturer="Texas Instruments"
Logo4: library part CMP-0074847-1, "FCC_disclaimer"
Logo5: library part CMP-0074769-4, Manufacturer="Texas Instruments"
R1 R5 R25 R26: library part CMP-0092204-1, "100 kOhms ±1% 0.063W, 1/16W Chip Resistor 0402 (1005 Metric)  Thick Film", Digikey Part Number=541-3960-1-ND, Manufacturer=Vishay, Mouser Part Number=71-CRCW0402100KFKEDC, Operating Temperature Range="-55°C to +155°C", Power_W=63mW, TempCo=100ppm/°C, Tolerance_%=1%
R2 R3 R4: library part CMP-0026694-1, "RES, 330, 1%, 0.1 W, AEC-Q200 Grade 0, 0402", Manufacturer=Panasonic, Power_W=100mW, Supplier Part Number 1=P330LCT-ND, TempCo="100 ppm/C", Tolerance_%=1%, Value2=0.1W, Value_Code=330R, ValueDisplayed=330
R6 R13 R21: library part CMP-0026732-1, "RES, 33.0, 1%, 0.062 W, 0402", Manufacturer="Yageo America", Power_W=62mW, Supplier Part Number 1=311-33.0LRCT-ND, TempCo="100 ppm/C", Tolerance_%=1%, Value2=0.062W, Value_Code=33R0, ValueDisplayed=33.0
R7 R8 R16 R17: library part CMP-0128762-1, "Res Thin Film 0402 91K Ohm 0.1% 0.063W ±25ppm/°C Molded SMD Punched Carrier T/R", Digikey Part Number=P91KDCCT-ND, Manufacturer=Panasonic, Mouser Part Number=667-ERA-2AEB913X, Operating Temperature Range="-55°C to +155°C", Power_W=63mW, TempCo=25ppm/°C, Tolerance_%=0.1%
R9 R15: library part CMP-0121025-1, "22 kOhms ±0.1% 0.063W, 1/16W Chip Resistor 0402 (1005 Metric) Automotive AEC-Q200 Thin Film", Digikey Part Number=P22KDCCT-ND, Manufacturer=Panasonic, Mouser Part Number=667-ERA-2AEB223X, Operating Temperature Range="-55°C to +155°C", Power_W=63mW, TempCo=25ppm/°C, Tolerance_%=0.1%
R10 R11 R12: library part CMP-0018811-2, "RES, 330 k, 0.1%, 1 W, 1206", Manufacturer="Vishay Draloric", Power_W=1W, Supplier Part Number 1=541-2312-1-ND, TempCo="25 ppm/C", Tolerance_%=0.1%, Value_Code=330k
R14: library part CMP-0024089-3, "RES, 2.00 k, 0.1%, 0.1 W, 0603", Manufacturer="Yageo America", Power_W=100mW, Supplier Part Number 1=603-RT0603BRD072KL, TempCo="25 ppm/C", Tolerance_%=0.1%, Value2=0.1W, Value_Code=2k00, ValueDisplayed=2.00k
R18 R19 R22 R24: library part CMP-0092058-1, "High Precision-High Stability Chip Resistor Thin Film 0402 41.2kOhm 0.1% Paper T/R", Digikey Part Number=YAG4262CT-ND, Manufacturer=Yageo, Mouser Part Number=603-RT0402BRD0741K2L, Operating Temperature Range="-55°C to +155°C", Power_W=63mW, TempCo=25ppm/°C, Tolerance_%=0.1%
R20 R23: library part CMP-0026770-1, "RES, 1.00 k, 0.1%, 0.063 W, 0402", Manufacturer=Panasonic, Power_W=63mW, Supplier Part Number 1=P1.0KDCCT-ND, TempCo="25 ppm/C", Tolerance_%=0.1%, Value2=0.063W, Value_Code=1k00, ValueDisplayed=1.00k
R27: library part CMP-0120311-1, "Res Thick Film 0402 8.2K Ohm 1% 0.063W(1/16W) ±100ppm/°C Pad SMD T/R", Digikey Part Number=311-8.20KLRCT-ND, Manufacturer=Yageo, Mouser Part Number=603-RC0402FR-078K2L, Operating Temperature Range="-55°C to +155°C", Power_W=63mW, TempCo=100ppm/°C, Tolerance_%=1%
R28: library part CMP-0026323-2, "RES, 38.3 k, 1%, 0.063 W, AEC-Q200 Grade 0, 0402", Manufacturer=Vishay-Dale, Power_W=63mW, Supplier Part Number 1=541-38.3KLCT-ND, TempCo="100 ppm/C", Tolerance_%=1%, Value2=0.063W, Value_Code=38k3, ValueDisplayed=38.3k
R29: library part CMP-0026658-1, "RES, 10.0 k, 1%, 0.1 W, 0402", Manufacturer=Panasonic, Power_W=100mW, Supplier Part Number 1=P10.0KLCT-ND, TempCo="100 ppm/C", Tolerance_%=1%, Value2=0.1W, Value_Code=10k0, ValueDisplayed=10.0k
SW1: library part CMP-0128770-1, "Tactile Switch SPST-NO Top Actuated Surface Mount", Coil Resistance_ohm=100mΩ, Contact Current Rating=50mA, Digikey Part Number=732-430133050816CT-ND, Manufacturer=Wurth, Mouser Part Number=710-430133050816, Operating Force=160gf, Operating Temperature Range="-40°C to +125°C"
TP1 TP2 TP3 TP4 TP5 TP6 TP7 TP8 TP9 TP10 TP11: library part CMP-0003825-1, "1mm Test Point, SMT", Manufacturer=Any
U1: library part CMP-0121694-1, "SimpleLink™ Bluetooth ® 5.3 Low Energy Wireless MCU, VQFN40", Frequency_Fixed=48MHz, Manufacturer="Texas Instruments", Max Supply Voltage=3.8V, Min Supply Voltage=1.71V, Operating Temperature Range="-40°C to +125°C"
U2 U3: library part CMP-0043099-3, "Low-Capacitance 2-Channel +/-15kV ESD Protection Array for High-Speed Data Interfaces, DRY0006A (USON-6)", Breakdown Voltage(Min)(V)=11, IO Capacitance(Typ)(pF)=1.5, IO Leakage Current(nA)=1, Manufacturer="Texas Instruments", Operating Temperature Range="-40 to 85 C", Rating=Catalog
U4: library part CMP-0086102-1, "TLV9002IDDFR, DDF0008A (SOT-23-THN-8)", Alternate Manufacturer="Texas Instruments", PartNumber=OPA2323IDDFR
U5: library part CMP-0097135-1, "4-A Brushed DC Motor Driver with Integrated Current Sense, Current Regulation and Stall Detection", Manufacturer="Texas Instruments", Max Supply Voltage=11V, Min Supply Voltage=1.65V, Nominal Supply Current=1.2mA, Operating Temperature Range="-40°C to +150°C", Switching Frequency=100kHz
U6: library part CMP-0074092-2, "700-V Lowest Quiescent Current Off-Line Switcher, D0007A (SOIC-7)", Alternate Manufacturer="Texas Instruments", Alternate PartNumber=UCC28881D
U7: library part CMP-0034271-1, "150-mA 30-V low-dropout (LDO) linear regulator with 3.2-μA supply current 5-SOT-23 -40 to 125", Digikey Part Number=296-TLV709A33DBVRCT-ND, Dropout Voltage=1000mV, Manufacturer="Texas Instruments", Max Supply Voltage=30V, Min Supply Voltage=4.3V, Mouser Part Number=595-TLV709A33DBVR, Nominal Supply Current=3.2uA, Operating Temperature Range="-40°C to +125°C", Output Voltage=3.3V
Y1: library part CMP-0001392-1, "Crystal Unit SMD 2.0x1.6 48.0MHz", Frequency Stability=30ppm, Frequency Tolerance=5ppm, Frequency_Fixed=48MHz, Load Capacitance=7pF, Manufacturer="TAI-SAW Thechnology", Operating Temperature Range="-40°C to +125°C"
Z1: library part CMP-0080187-3, "Inductor, Multilayer, Air Core, 1.9 nH, 1 A, 0.05 ohm, AEC-Q200 Grade 1, SMD", Manufacturer=MuRata, Value1="0.05 ohm", Value2=1A, ValueDisplayed=1.9nH
ZZ1: library part CMP-0077236-1
ZZ2: library part CMP-0077237-1
ZZ3: library part CMP-0077238-1

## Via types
v1: diameter 0.5, hole 0.3, Top Layer to Bottom Layer, tented both sides, 186 vias
v2: diameter 0.443, hole 0.3, Top Layer to Bottom Layer, tented both sides, 4 vias

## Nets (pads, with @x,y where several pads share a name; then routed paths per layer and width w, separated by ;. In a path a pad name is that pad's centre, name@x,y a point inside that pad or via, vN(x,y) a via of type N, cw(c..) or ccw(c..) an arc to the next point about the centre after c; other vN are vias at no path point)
3.3V: C7.1 C8.1 C9.1 C10.1 C11.1 C18.1 C34.1 D2.4 D4.1 J1.5 R1.2 R5.2 R16.2 R22.1 TP11.1 U1.8 U1.17 U1.31 U1.38 U2.1 U3.1 U4.8 U7.5 | length 23.5
  Top Layer w0.102: v1(40.6,13.675) TP11.1@40.6,13.725 ; v1@41.1,14.225 v1(41.1,14.275)
  Top Layer w0.2: D2.4@1.7,11.975 v1(2.225,11.975) ; v1(6.1,8.775) 6.117,8.775 6.367,9.025 6.625,9.025 6.725,9.125 R5.2@6.725,9.225 R1.2@6.725,10.525 ; U3.1@12.975,16.275 12.975,16.318 13.025,16.368 13.418,16.368 v1(13.475,16.425) ; U2.1@12.975,18.4 12.975,18.475 13.025,18.525 13.45,18.525 v1(13.475,18.5) ; v1(15.6,10.4) 15.657,10.457 15.657,10.707 16.35,11.4 C10.1@16.45,11.4 16.475,11.425 U1.38@18.45,11.425 ; v1(16,15.8) 16,15.719 16.15,15.569 16.15,14.975 16.35,14.775 C9.1@16.55,14.775 ; C9.1@16.45,14.775 C9.1@16.55,14.775 ; U1.31@18.45,14.225 17.1,14.225 C9.1@16.55,14.775 ; U1.8@21.85,10.025 21.85,9.3 22.675,8.475 C7.1@22.775,8.475 v1(23.373,8.475) ; U1.17@23.25,13.025 23.793,13.025 23.943,12.875 24.875,12.875 24.925,12.825 C8.1@24.9,12.8 ; R22.1@25.162,4.629 v1(25.162,5.262) ; U4.8@28.425,2.85 28.7,2.85 29.175,2.375 C18.1@29.175,1.6 v1(29.175,0.825) ; R16.2@32.502,6.037 v1(33.163,6.037) ; v1(34.825,5.925) D4.1@35.605,5.925
  Top Layer w0.3: C8.1@24.9,12.8 24.963,12.8 24.963,11.713 C11.1@24.875,11.625 24.875,11.55 v1(25.4,11.025)
  Bottom Layer w0.2: v1@6.025,8.775 v1(6.1,8.775) ; J1.5@10.87,7.17 v1(10.87,8.47) ; v1(23.373,8.475) v1@23.398,8.5
  other v1: 41.4,13.675 42.2,13.675 41.9,14.275 42.7,14.275
5V: C23.1 C24.1 C25.1 C31.1 C32.1 C33.1 C35.1 D1.1 D5.2 D7.1 L3.2 TP10.1 U5.1 U7.1 | length 11.6
  Top Layer w0.6: C23.1@35.048,9.775 C24.1@36.4,9.775 36.411,9.764 36.411,8.414 38.6,6.225 TP10.1@44.35,6.225
DRV_FB_I: C26.1 R27.2 TP9.1 U1.23 U5.8 | length 18.1
  Top Layer w0.15: U1.23@21.85,14.825 21.85,15.3 22.075,15.525 22.5,15.525 23.1,16.125 C26.1@23.1,16.225 28.025,16.225 30.625,13.625 30.625,12.545 TP9.1@31.67,11.5 32.195,10.975 33.695,10.975 34.17,11.45 R27.2@34.17,11.5 ; R27.2@34.17,11.55 34.625,12.005 34.625,12.48 34.995,12.85 U5.8@35.12,12.85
